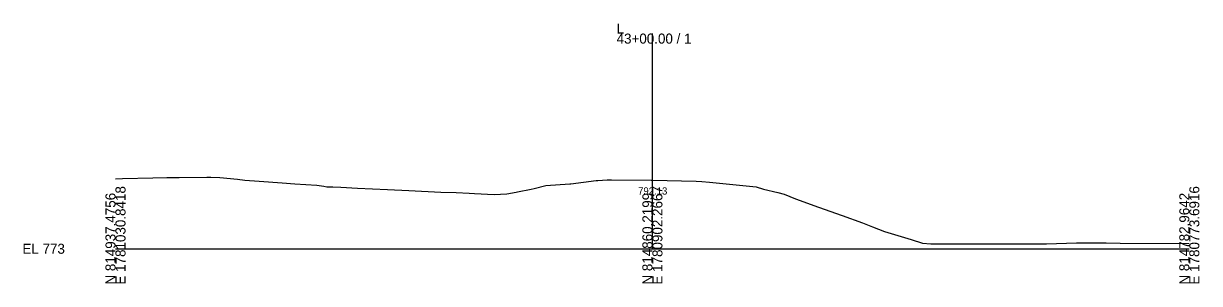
# Model space of a CAD drawing. Extents: x -26 to 7903, y -10 to 9573.
# Drawn here: x 974.3 to 1302.8, y 3990.3 to 4062.9 of the extents above; entities that cross this region are included whole.
import ezdxf

# ---------------------------------------------------------------- set-up
doc = ezdxf.new("R2010")
doc.units = 0
for name, color, linetype in [('Exist Cross Section Cell', 7, 'Continuous'), ('Exist XS Center Line Elevation Label', 7, 'Continuous'), ('Exist XS Ground Line', 7, 'Continuous')]:
    doc.layers.add(name, color=color, linetype=linetype)

msp = doc.modelspace()

# ---------------------------------------------------------------- linework, layer by layer
at = {"layer": 'Exist Cross Section Cell'}
for p, q in [((1150, 4000), (1150, 4060.07)), ((1000, 4000), (1150, 4000)), ((1150, 4000), (1300, 4000))]:
    msp.add_line(p, q, dxfattribs=at)
at = {"layer": 'Exist XS Ground Line'}
for p, q in [((1000, 4019.53), (1001.96, 4019.62)), ((1001.96, 4019.62), (1010.4, 4019.8)), ((1010.4, 4019.8), (1014.37, 4019.88)), ((1014.37, 4019.88), (1017.81, 4019.92)), ((1017.81, 4019.92), (1025.49, 4020.02)), ((1025.49, 4020.02), (1026.67, 4019.98)), ((1026.67, 4019.98), (1029.11, 4019.89)), ((1029.11, 4019.89), (1034.09, 4019.41)), ((1034.09, 4019.41), (1036.18, 4019.15)), ((1036.18, 4019.15), (1040.11, 4018.9)), ((1040.11, 4018.9), (1046.53, 4018.38)), ((1046.53, 4018.38), (1050.14, 4018.13)), ((1050.14, 4018.13), (1056.26, 4017.73)), ((1120.21, 4017.63), (1126.91, 4018.1)), ((1126.91, 4018.1), (1127.25, 4018.13)), ((1127.25, 4018.13), (1134.29, 4019.04)), ((1134.29, 4019.04), (1134.76, 4019.09)), ((1134.76, 4019.09), (1137.33, 4019.2)), ((1137.33, 4019.2), (1138.6, 4019.26)), ((1138.6, 4019.26), (1149.66, 4019.13)), ((1149.66, 4019.13), (1150, 4019.13)), ((1150, 4019.13), (1162.19, 4018.82)), ((1162.19, 4018.82), (1163.8, 4018.73)), ((1163.8, 4018.73), (1165.97, 4018.61)), ((1165.97, 4018.61), (1177.16, 4017.48)), ((1056.26, 4017.73), (1058.17, 4017.46)), ((1058.17, 4017.46), (1059, 4017.33)), ((1059, 4017.33), (1060.71, 4017.27)), ((1060.71, 4017.27), (1062.94, 4017.19)), ((1062.94, 4017.19), (1067.57, 4016.93)), ((1067.57, 4016.93), (1075.95, 4016.56)), ((1075.95, 4016.56), (1081.95, 4016.23)), ((1081.95, 4016.23), (1090.91, 4015.79)), ((1090.91, 4015.79), (1095.14, 4015.67)), ((1095.14, 4015.67), (1098.77, 4015.53)), ((1098.77, 4015.53), (1100.3, 4015.46)), ((1100.3, 4015.46), (1105.83, 4015.12)), ((1105.83, 4015.12), (1109.34, 4015.37)), ((1109.34, 4015.37), (1111.97, 4015.84)), ((1111.97, 4015.84), (1112.3, 4015.9)), ((1112.3, 4015.9), (1116.16, 4016.62)), ((1116.16, 4016.62), (1116.95, 4016.81)), ((1116.95, 4016.81), (1120.21, 4017.63)), ((1177.16, 4017.48), (1179.01, 4017.33)), ((1179.01, 4017.33), (1181.04, 4016.67)), ((1181.04, 4016.67), (1185.04, 4015.66)), ((1185.04, 4015.66), (1186.78, 4015.22)), ((1186.78, 4015.22), (1189.98, 4013.94)), ((1189.98, 4013.94), (1196.44, 4011.62)), ((1196.44, 4011.62), (1203.01, 4009.26)), ((1203.01, 4009.26), (1208.71, 4007.2)), ((1208.71, 4007.2), (1211.46, 4006.14)), ((1211.46, 4006.14), (1214.88, 4004.77)), ((1214.88, 4004.77), (1222.26, 4002.61)), ((1222.26, 4002.61), (1225.49, 4001.59)), ((1225.49, 4001.59), (1227.79, 4001.35)), ((1260.11, 4001.33), (1268.5, 4001.61)), ((1268.5, 4001.61), (1276.73, 4001.62)), ((1276.73, 4001.62), (1280.65, 4001.59)), ((1280.65, 4001.59), (1300, 4001.42)), ((1227.79, 4001.35), (1229.89, 4001.41)), ((1229.89, 4001.41), (1235.03, 4001.4)), ((1235.03, 4001.4), (1260.11, 4001.33))]:
    msp.add_line(p, q, dxfattribs=at)

# ---------------------------------------------------------------- texts
at = {"layer": 'Exist Cross Section Cell'}
for s, p in [('L', (1140, 4060.07)), ('43+00.00 / 1', (1140, 4057.27)), ('EL 773', (974, 3998.6))]:
    msp.add_text(s, height=2.8, dxfattribs=at).set_placement(p)
for s, p in [('N 814937.4756', (1000, 3990)), ('E 1781030.8418', (1002.8, 3990)), ('N 814860.2199', (1150, 3990)), ('E 1780902.2667', (1152.8, 3990)), ('N 814782.9642', (1300, 3990)), ('E 1780773.6916', (1302.8, 3990))]:
    msp.add_text(s, height=2.8, rotation=90, dxfattribs=at).set_placement(p)
at = {"layer": 'Exist XS Center Line Elevation Label'}
msp.add_text('792.13', height=2, dxfattribs=at).set_placement((1145.99, 4015.13))

doc.saveas('drawing.dxf')
